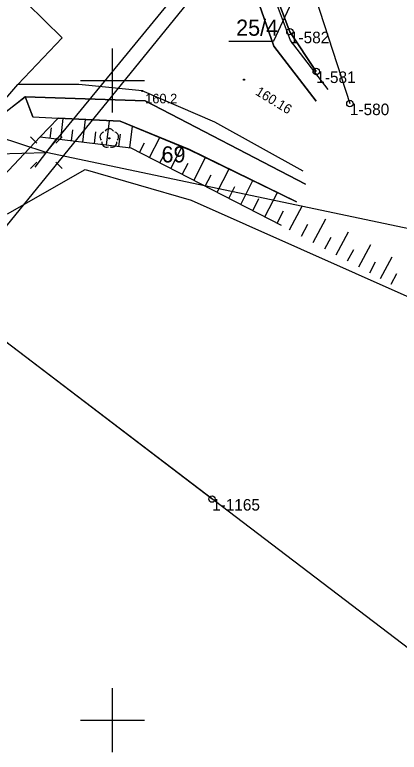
# Model space of a CAD drawing. Extents: x 5598798 to 5599616, y 5661498 to 5662453.
# Drawn here: x 5599092.4 to 5599122.4, y 5661547.5 to 5661605.1 of the extents above; entities that cross this region are included whole.
import ezdxf

# ---------------------------------------------------------------- set-up
doc = ezdxf.new("R2010")
doc.units = 0
for name, color, linetype in [('BUBZ_L_1', 7, 'Continuous'), ('Dzialki', 7, 'Continuous'), ('Kontury', 7, 'Continuous'), ('KTCR_L_1', 7, 'Continuous'), ('KTJZ_L_0', 7, 'Continuous'), ('KTKR_L_0', 7, 'Continuous'), ('Numery_dzialek', 7, 'Continuous'), ('Numery_punktow', 7, 'Continuous'), ('OBOP_T_1', 7, 'Continuous'), ('Podzial_sekcyjny_krzyze', 7, 'Continuous'), ('PTRW_L_1', 7, 'Continuous'), ('Punkty', 7, 'Continuous'), ('RTPW_T_0', 7, 'Continuous'), ('RTPW_T_1', 7, 'Continuous'), ('SUPE_L_3', 7, 'Continuous'), ('SUPW_L_0', 7, 'Continuous'), ('SUSM_L_4', 7, 'Continuous'), ('SUSM_T_0', 7, 'Continuous'), ('Uzytki', 7, 'Continuous')]:
    doc.layers.add(name, color=color, linetype=linetype)

# ---------------------------------------------------------------- blocks, each defined once
blk = doc.blocks.new('GRT')
blk.add_circle((0, 0), 0.25)
blk = doc.blocks.new('2_OBOP02_01')
blk.add_circle((0, 0), 0.045)
for centre, start, end in [((0, 0.375056), 30.140124, 149.859876), ((-0.356659, 0.115892), 102.144465, 221.860023), ((0.356659, 0.115892), 318.139977, 77.855535), ((-0.220404, -0.303384), 174.148182, 293.854228), ((0.220404, -0.303384), 246.145772, 5.851818)]:
    blk.add_arc(centre, 0.375, start, end)
blk = doc.blocks.new('2_RTPW02')
blk.add_circle((0, 0), 0.045)
blk = doc.blocks.new('2_RTPW01')
blk.add_circle((0, 0), 0.045)
blk = doc.blocks.new('4_SUSM01_01')
for p, q in [((-0.74249, 0.74249), (-1.23746, 1.23746)), ((0.74249, 0.74249), (1.23746, 1.23746)), ((-0.74249, -0.74249), (-1.23746, -1.23746)), ((0.74249, -0.74249), (1.23746, -1.23746))]:
    blk.add_line(p, q)

msp = doc.modelspace()

# ---------------------------------------------------------------- linework, layer by layer
at = {"layer": 'BUBZ_L_1'}
for p, q in [((5599095.76113, 5661597.058358), (5599094.36359, 5661595.600952)), ((5599100.60838, 5661596.821618), (5599095.76113, 5661597.058358)), ((5599095.956673, 5661595.405304), (5599096.15731, 5661597.039008)), ((5599097.685101, 5661595.193034), (5599097.901346, 5661596.95383)), ((5599099.54799, 5661594.96425), (5599099.781057, 5661596.862025)), ((5599106.03914, 5661594.602598), (5599100.60838, 5661596.821618)), ((5599095.139821, 5661595.505622), (5599095.238366, 5661596.308039)), ((5599096.804703, 5661595.301156), (5599096.908851, 5661596.149186)), ((5599098.599102, 5661595.080784), (5599098.711352, 5661595.994785)), ((5599101.352962, 5661594.742579), (5599101.560512, 5661596.432575)), ((5599094.36359, 5661595.600952), (5599101.448364, 5661594.730863)), ((5599100.507964, 5661594.846355), (5599100.62586, 5661595.806329)), ((5599102.899471, 5661593.984301), (5599103.707681, 5661595.555237)), ((5599102.114003, 5661594.388407), (5599102.500432, 5661595.139516)), ((5599104.579839, 5661593.11979), (5599105.463681, 5661594.837732)), ((5599101.448364, 5661594.730863), (5599113.19213, 5661588.688961)), ((5599103.720868, 5661593.561711), (5599104.143459, 5661594.383108)), ((5599114.389664, 5661590.514929), (5599106.03914, 5661594.602598)), ((5599106.36158, 5661592.203124), (5599107.282839, 5661593.993794)), ((5599105.466246, 5661592.663754), (5599105.922282, 5661593.55016)), ((5599108.179396, 5661591.267899), (5599109.119307, 5661593.094824)), ((5599107.265934, 5661591.737855), (5599107.731203, 5661592.642208)), ((5599110.034016, 5661590.313739), (5599110.992957, 5661592.177653)), ((5599109.102059, 5661590.79321), (5599109.576748, 5661591.715873)), ((5599111.926185, 5661589.340261), (5599112.904541, 5661591.241912)), ((5599110.975359, 5661589.829439), (5599111.459659, 5661590.770783)), ((5599113.840683, 5661588.341404), (5599114.860399, 5661590.244231)), ((5599112.886588, 5661588.846155), (5599113.380693, 5661589.806558)), ((5599115.701629, 5661587.344132), (5599116.691493, 5661589.191255)), ((5599114.778067, 5661587.839065), (5599115.280407, 5661588.776449)), ((5599117.508096, 5661586.376055), (5599118.468983, 5661588.169105)), ((5599116.611571, 5661586.856498), (5599117.099205, 5661587.766441)), ((5599118.391401, 5661585.902696), (5599118.86476, 5661586.786001)), ((5599119.261681, 5661585.436317), (5599120.194439, 5661587.176877)), ((5599120.963931, 5661584.52409), (5599121.869382, 5661586.213695)), ((5599120.119128, 5661584.976815), (5599120.578629, 5661585.834262)), ((5599121.796276, 5661584.07804), (5599122.242326, 5661584.910385))]:
    msp.add_line(p, q, dxfattribs=at)
at = {"layer": 'Dzialki'}
for p, q in [((5599087.14, 5661583.01), (5599113.12, 5661614.97)), ((5599113.12, 5661614.97), (5599118.57, 5661598.2)), ((5599112.62, 5661607.12), (5599113.88, 5661603.82)), ((5599113.88, 5661603.82), (5599115.94, 5661600.71)), ((5599107.79, 5661567.29), (5599087.14, 5661583.01))]:
    msp.add_line(p, q, dxfattribs=at)
at = {"layer": 'Kontury'}
for p, q in [((5599113.88, 5661603.82), (5599112.62, 5661607.12)), ((5599115.94, 5661600.71), (5599113.88, 5661603.82)), ((5599127.28, 5661552.45), (5599087.14, 5661583.01))]:
    msp.add_line(p, q, dxfattribs=at)
at = {"layer": 'KTCR_L_1'}
for p, q in [((5599113.93, 5661603.13), (5599112.09, 5661608.11)), ((5599110.86, 5661607.74), (5599112.63, 5661602.7)), ((5599116.86, 5661599.31), (5599113.93, 5661603.13)), ((5599112.63, 5661602.7), (5599115.93, 5661598.38))]:
    msp.add_line(p, q, dxfattribs=at)
at = {"layer": 'KTJZ_L_0'}
for p, q in [((5599112.63, 5661602.7), (5599110.86, 5661607.74)), ((5599096.07, 5661603.33), (5599093.32, 5661606.04)), ((5599092.61, 5661599.7), (5599096.07, 5661603.33)), ((5599115.93, 5661598.38), (5599112.63, 5661602.7)), ((5599072.84, 5661577.03), (5599092.61, 5661599.7)), ((5599097.38, 5661599.7), (5599092.61, 5661599.7)), ((5599102.33, 5661599.19), (5599097.38, 5661599.7)), ((5599108, 5661596.76), (5599102.33, 5661599.19)), ((5599090.63, 5661596.78), (5599093.18, 5661598.74)), ((5599093.18, 5661598.74), (5599102.57, 5661598.42)), ((5599102.57, 5661598.42), (5599115.1, 5661591.91)), ((5599114.91, 5661592.92), (5599108, 5661596.76))]:
    msp.add_line(p, q, dxfattribs=at)
at = {"layer": 'KTKR_L_0'}
for p, q in [((5599110.86, 5661607.74), (5599112.63, 5661602.7)), ((5599112.63, 5661602.7), (5599115.93, 5661598.38))]:
    msp.add_line(p, q, dxfattribs=at)
at = {"layer": 'Numery_dzialek'}
for p in [(5599114.430511, 5661607.011873), (5599109.092044, 5661603.084648)]:
    msp.add_line(p, (5599112.603219, 5661603.084648), dxfattribs=at)
at = {"layer": 'Podzial_sekcyjny_krzyze'}
for p, q in [((5599100, 5661597.5), (5599100, 5661602.5)), ((5599097.5, 5661600), (5599102.5, 5661600)), ((5599100, 5661547.5), (5599100, 5661552.5)), ((5599097.5, 5661550), (5599102.5, 5661550))]:
    msp.add_line(p, q, dxfattribs=at)
at = {"layer": 'PTRW_L_1'}
for p, q in [((5599090.626974, 5661596.782226), (5599093.183537, 5661598.743348)), ((5599102.57, 5661598.42), (5599093.18, 5661598.74)), ((5599093.18, 5661598.74), (5599093.77, 5661597.16)), ((5599093.76749, 5661597.155727), (5599093.183537, 5661598.743348)), ((5599115.1, 5661591.91), (5599102.57, 5661598.42)), ((5599093.77, 5661597.16), (5599095.76, 5661597.06)), ((5599095.76113, 5661597.058358), (5599094.36359, 5661595.600952)), ((5599095.76, 5661597.06), (5599100.61, 5661596.82)), ((5599100.61, 5661596.82), (5599106.04, 5661594.6)), ((5599094.36359, 5661595.600952), (5599084.881522, 5661585.712704)), ((5599106.04, 5661594.6), (5599114.39, 5661590.51))]:
    msp.add_line(p, q, dxfattribs=at)
at = {"layer": 'SUPE_L_3'}
for p, q in [((5599094.830509, 5661594.368063), (5599125.304463, 5661631.572851)), ((5599094.830509, 5661594.368063), (5599064.625935, 5661604.291571)), ((5598996.482621, 5661592.032784), (5599094.830509, 5661594.368063)), ((5599142.263788, 5661584.415924), (5599094.830509, 5661594.368063))]:
    msp.add_line(p, q, dxfattribs=at)
at = {"layer": 'SUPW_L_0'}
for p, q in [((5599091.802605, 5661589.592031), (5599097.866615, 5661593.06142)), ((5599091.802605, 5661589.592031), (5599097.866615, 5661593.06142)), ((5599097.866615, 5661593.06142), (5599106.165307, 5661590.648806)), ((5599097.866615, 5661593.06142), (5599106.165307, 5661590.648806)), ((5599106.165307, 5661590.648806), (5599123.265858, 5661583.053706)), ((5599106.165307, 5661590.648806), (5599123.265858, 5661583.053706))]:
    msp.add_line(p, q, dxfattribs=at)
at = {"layer": 'SUSM_L_4'}
msp.add_line((5599093.970896, 5661593.233001), (5599095.690123, 5661595.503125), dxfattribs=at)
at = {"layer": 'Uzytki'}
for p, q in [((5599112.62, 5661607.12), (5599113.88, 5661603.82)), ((5599113.88, 5661603.82), (5599115.94, 5661600.71)), ((5599127.28, 5661552.45), (5599087.14, 5661583.01))]:
    msp.add_line(p, q, dxfattribs=at)

# ---------------------------------------------------------------- block references
at = {"layer": 'OBOP_T_1'}
msp.add_blockref('2_OBOP02_01', (5599099.755994, 5661595.480816), dxfattribs=at)
at = {"layer": 'Punkty'}
for p in [(5599113.88, 5661603.82), (5599115.94, 5661600.71), (5599118.57, 5661598.2), (5599107.79, 5661567.29)]:
    msp.add_blockref('GRT', p, dxfattribs=at)
at = {"layer": 'RTPW_T_0', "rotation": -3.0000000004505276e-06}
msp.add_blockref('2_RTPW01', (5599102.33, 5661599.19), dxfattribs=at)
at = {"layer": 'RTPW_T_1'}
msp.add_blockref('2_RTPW02', (5599110.291928, 5661600.067134), dxfattribs=at)
at = {"layer": 'SUSM_T_0'}
msp.add_blockref('4_SUSM01_01', (5599094.830509, 5661594.368063), dxfattribs=at)

# ---------------------------------------------------------------- texts
at = {"layer": 'Numery_dzialek'}
for s, p in [('25/4', (5599109.675987, 5661603.504648)), ('69', (5599103.839361, 5661593.600317))]:
    msp.add_text(s, height=1.26, dxfattribs=at).set_placement(p)
at = {"layer": 'Numery_punktow'}
for s, p in [('1-582', (5599113.88, 5661602.92)), ('1-581', (5599115.94, 5661599.81)), ('1-580', (5599118.57, 5661597.3)), ('1-1165', (5599107.79, 5661566.39))]:
    msp.add_text(s, height=0.9, dxfattribs=at).set_placement(p)
at = {"layer": 'RTPW_T_0'}
msp.add_text('160.2', height=0.75, dxfattribs=at).set_placement((5599102.56, 5661598.22))
at = {"layer": 'RTPW_T_1'}
msp.add_text('160.16', height=0.75, rotation=328.66231, dxfattribs=at).set_placement((5599111.12129, 5661598.939202))

doc.saveas('drawing.dxf')
